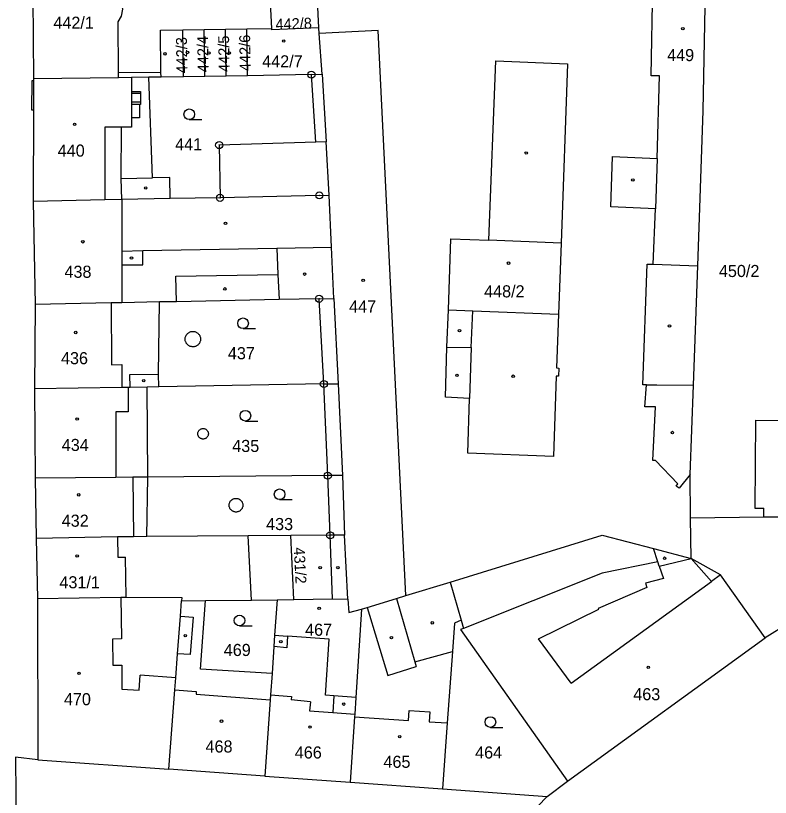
# Model space of a CAD drawing. Extents: x -733394 to -722299, y -1082822 to -1075049.
# Drawn here: x -728472.7 to -728366.6, y -1079581.1 to -1079471.2 of the extents above; entities that cross this region are included whole.
import ezdxf

# ---------------------------------------------------------------- set-up
doc = ezdxf.new("R2010")
doc.units = 0
for name, color, linetype in [('Hranice parcel', 7, 'Continuous'), ('Parcelní čísla', 7, 'Continuous'), ('Vnitřní kresba', 7, 'Continuous'), ('Značky bodu BP', 7, 'Continuous'), ('Značky budov', 7, 'Continuous'), ('Značky kultur', 7, 'Continuous')]:
    doc.layers.add(name, color=color, linetype=linetype)

msp = doc.modelspace()

# ---------------------------------------------------------------- linework, layer by layer
at = {"layer": 'Hranice parcel'}
for p, q in [((-728470.32, -1079459.36), (-728470.14, -1079480.06)), ((-728436.69, -1079472.97), (-728436.85, -1079469.29)), ((-728430.09, -1079472.87), (-728430.25, -1079469.02)), ((-728449.18, -1079473.15), (-728446.18, -1079473.11)), ((-728449.09, -1079479.75), (-728449.18, -1079473.15)), ((-728446.18, -1079473.11), (-728443.18, -1079473.06)), ((-728446.09, -1079479.71), (-728446.18, -1079473.11)), ((-728443.18, -1079473.06), (-728440.18, -1079473.02)), ((-728443.09, -1079479.66), (-728443.18, -1079473.06)), ((-728440.18, -1079473.02), (-728436.69, -1079472.97)), ((-728440.09, -1079479.62), (-728440.18, -1079473.02)), ((-728430.03, -1079473.65), (-728430.09, -1079472.87)), ((-728458.24, -1079479.88), (-728470.14, -1079480.06)), ((-728452.24, -1079479.8), (-728453.95, -1079479.8)), ((-728449.09, -1079479.75), (-728452.24, -1079479.8)), ((-728446.09, -1079479.71), (-728449.09, -1079479.75)), ((-728443.09, -1079479.66), (-728446.09, -1079479.71)), ((-728440.09, -1079479.62), (-728443.09, -1079479.66)), ((-728431.11, -1079479.45), (-728440.09, -1079479.62)), ((-728430.49, -1079488.97), (-728431.11, -1079479.45)), ((-728470.19, -1079497.28), (-728469.94, -1079511.77)), ((-728429.36, -1079522.95), (-728430.03, -1079510.97)), ((-728469.94, -1079511.77), (-728470.02, -1079523.65)), ((-728452.57, -1079523.35), (-728454.17, -1079523.38)), ((-728454.11, -1079536.05), (-728454.17, -1079523.38)), ((-728429.36, -1079522.95), (-728452.57, -1079523.35)), ((-728428.81, -1079535.84), (-728429.36, -1079522.95)), ((-728470.02, -1079523.65), (-728469.93, -1079536.19)), ((-728469.93, -1079536.19), (-728469.77, -1079544.69)), ((-728454.25, -1079544.41), (-728454.11, -1079536.05)), ((-728428.81, -1079535.84), (-728454.11, -1079536.05)), ((-728428.47, -1079544.23), (-728428.81, -1079535.84)), ((-728377.86, -1079541.79), (-728377.89, -1079535.66)), ((-728335.66, -1079539.03), (-728367.36, -1079558.62)), ((-728377.75, -1079547.49), (-728377.86, -1079541.79)), ((-728428.17, -1079553.18), (-728428.47, -1079544.23)), ((-728469.77, -1079544.69), (-728469.62, -1079553.11)), ((-728439.98, -1079544.31), (-728454.25, -1079544.41)), ((-728439.55, -1079553.33), (-728439.98, -1079544.31)), ((-728417.86, -1079552.71), (-728411.64, -1079550.81)), ((-728411.64, -1079550.81), (-728410.09, -1079556.17)), ((-728469.62, -1079553.11), (-728469.57, -1079575.82)), ((-728449.37, -1079553.45), (-728445.98, -1079553.41)), ((-728445.98, -1079553.41), (-728439.55, -1079553.33)), ((-728439.55, -1079553.33), (-728435.93, -1079553.28)), ((-728424.06, -1079554.6), (-728424.87, -1079567.02)), ((-728395.11, -1079578.82), (-728367.36, -1079558.62)), ((-728436.39, -1079559.88), (-728436.65, -1079563.67)), ((-728469.57, -1079575.82), (-728451.13, -1079577.12)), ((-728437.66, -1079578.09), (-728451.13, -1079577.12)), ((-728437.66, -1079578.09), (-728425.65, -1079578.94)), ((-728425.65, -1079578.94), (-728412.71, -1079579.86)), ((-728398.01, -1079580.93), (-728395.11, -1079578.82)), ((-728412.71, -1079579.86), (-728398.01, -1079580.93)), ((-728398.01, -1079580.93), (-728407.52, -1079590.83))]:
    msp.add_line(p, q, dxfattribs=at)
for points in [[(-728377.89, -1079535.66), (-728379.46, -1079537.61), (-728379.86, -1079537.3), (-728379.63, -1079537), (-728382.77, -1079533.71), (-728383.15, -1079533.73), (-728382.75, -1079526.18), (-728384.26, -1079526.14), (-728384.05, -1079523.07), (-728384.55, -1079523.06), (-728383.93, -1079506.08), (-728383.08, -1079506.09), (-728382.78, -1079498.3), (-728389.06, -1079498.02), (-728388.8, -1079490.97), (-728382.54, -1079491.22), (-728382.21, -1079479.61), (-728383.37, -1079479.6), (-728382.92, -1079454.06), (-728382.9, -1079452.81), (-728381.27, -1079452.84), (-728381.29, -1079454.07), (-728375.5, -1079454.1)], [(-728458.24, -1079479.88), (-728458.24, -1079479.17), (-728458.28, -1079472.03), (-728457.78, -1079471.24), (-728457.59, -1079470.26), (-728457.79, -1079469.27), (-728458.3, -1079468.49), (-728458.34, -1079460.95)], [(-728377.89, -1079535.66), (-728377.44, -1079523.13), (-728376.84, -1079506.33), (-728376.06, -1079484.54), (-728375.78, -1079469.87)], [(-728452.24, -1079479.8), (-728452.25, -1079479.09), (-728452.33, -1079473.2), (-728449.18, -1079473.15)], [(-728430.09, -1079472.87), (-728436.69, -1079473.14), (-728436.69, -1079472.97)], [(-728431.11, -1079479.45), (-728429.6, -1079479.37), (-728430.03, -1079473.65)], [(-728417.86, -1079552.71), (-728421.74, -1079473.24), (-728430.03, -1079473.65)], [(-728396.38, -1079521.86), (-728396.71, -1079521.85), (-728397.12, -1079533.13), (-728409.15, -1079532.69), (-728408.9, -1079525.01), (-728412.29, -1079524.82), (-728412.07, -1079517.77), (-728411.86, -1079512.54), (-728411.51, -1079502.52), (-728406.17, -1079502.74), (-728405.22, -1079477.52), (-728395.12, -1079477.92), (-728396.03, -1079503.15), (-728396.39, -1079513.11), (-728396.67, -1079520.7), (-728396.34, -1079520.71), (-728396.38, -1079521.86)], [(-728470.14, -1079480.06), (-728470.14, -1079480.32), (-728470.15, -1079484.39), (-728470.19, -1079497.28)], [(-728453.95, -1079479.8), (-728456.4, -1079479.85), (-728458.24, -1079479.88)], [(-728450.95, -1079496.87), (-728451.01, -1079493.91), (-728453.42, -1079493.97), (-728453.95, -1079479.8)], [(-728430.49, -1079488.97), (-728444.07, -1079489.36), (-728443.95, -1079496.78), (-728450.95, -1079496.87)], [(-728430.03, -1079510.97), (-728427.96, -1079510.93), (-728428.29, -1079503.71), (-728428.62, -1079496.4), (-728429.05, -1079488.91), (-728430.49, -1079488.97)], [(-728450.95, -1079496.87), (-728457.76, -1079497.02), (-728460.16, -1079497.07), (-728470.19, -1079497.28)], [(-728430.03, -1079510.97), (-728435.66, -1079511.09), (-728450.08, -1079511.38), (-728452.47, -1079511.42)], [(-728452.47, -1079511.42), (-728457.73, -1079511.53), (-728459.27, -1079511.56), (-728469.94, -1079511.77)], [(-728452.57, -1079523.35), (-728452.6, -1079521.55), (-728452.47, -1079511.42)], [(-728454.17, -1079523.38), (-728456.59, -1079523.42), (-728456.86, -1079523.42), (-728457.73, -1079523.44), (-728470.02, -1079523.65)], [(-728454.11, -1079536.05), (-728456.21, -1079536.07), (-728458.59, -1079536.09), (-728469.93, -1079536.19)], [(-728377.86, -1079541.79), (-728367.56, -1079541.61), (-728364.95, -1079541.61)], [(-728428.47, -1079544.23), (-728433.99, -1079544.27), (-728439.98, -1079544.31)], [(-728411.64, -1079550.81), (-728390.24, -1079544.2), (-728383.07, -1079546.09), (-728377.75, -1079547.49)], [(-728454.25, -1079544.41), (-728456.12, -1079544.42), (-728458.35, -1079544.44), (-728469.77, -1079544.69)], [(-728367.36, -1079558.62), (-728373.64, -1079549.8), (-728377.75, -1079547.49)], [(-728469.62, -1079553.11), (-728457.87, -1079552.94), (-728457.16, -1079552.94), (-728449.34, -1079552.99), (-728449.37, -1079553.45)], [(-728424.06, -1079554.6), (-728423.29, -1079554.37), (-728419.14, -1079553.1), (-728417.86, -1079552.71)], [(-728451.13, -1079577.12), (-728450.3, -1079565.95), (-728450.18, -1079564.26), (-728449.92, -1079560.87), (-728449.53, -1079555.61), (-728449.37, -1079553.45)], [(-728436.65, -1079563.67), (-728446.69, -1079563.03), (-728445.98, -1079553.41)], [(-728435.93, -1079553.28), (-728436.28, -1079558.28), (-728436.39, -1079559.88)], [(-728435.93, -1079553.28), (-728433.57, -1079553.25), (-728428.17, -1079553.18)], [(-728428.17, -1079553.18), (-728425.99, -1079553.21), (-728425.84, -1079555.09), (-728424.06, -1079554.6)], [(-728410.09, -1079556.17), (-728410.99, -1079556.59), (-728411.28, -1079560.58), (-728412.03, -1079570.61), (-728412.71, -1079579.86)], [(-728410.09, -1079556.17), (-728409.76, -1079557.31), (-728410.15, -1079557.47), (-728395.11, -1079578.82)], [(-728424.87, -1079567.02), (-728427.95, -1079566.8), (-728429.15, -1079566.71), (-728428.62, -1079558.81), (-728434.45, -1079558.41), (-728434.57, -1079560.04), (-728436.39, -1079559.88)], [(-728436.65, -1079563.67), (-728436.86, -1079566.68), (-728436.91, -1079567.34), (-728437.66, -1079578.09)], [(-728424.87, -1079567.02), (-728425.02, -1079569.36), (-728425.05, -1079569.76), (-728425.65, -1079578.94)], [(-728469.57, -1079575.82), (-728472.67, -1079575.42), (-728472.62, -1079586.13)]]:
    msp.add_lwpolyline(points, dxfattribs=at)
at = {"layer": 'Vnitřní kresba'}
for p, q in [((-728458.24, -1079479.17), (-728452.25, -1079479.09)), ((-728429.6, -1079479.37), (-728429.05, -1079488.91)), ((-728470.41, -1079480.32), (-728470.42, -1079484.39)), ((-728470.14, -1079480.32), (-728470.41, -1079480.32)), ((-728456.4, -1079479.85), (-728456.4, -1079481.81)), ((-728456.4, -1079481.81), (-728456.4, -1079482.11)), ((-728456.4, -1079481.81), (-728455.15, -1079481.81)), ((-728455.15, -1079482.11), (-728456.4, -1079482.11)), ((-728456.4, -1079482.11), (-728456.4, -1079483.34)), ((-728455.15, -1079481.81), (-728455.15, -1079482.11)), ((-728455.15, -1079482.11), (-728455.15, -1079483.34)), ((-728455.15, -1079483.34), (-728456.4, -1079483.34)), ((-728456.4, -1079483.34), (-728456.4, -1079483.64)), ((-728455.29, -1079483.64), (-728456.4, -1079483.64)), ((-728456.4, -1079483.64), (-728456.4, -1079485.51)), ((-728455.15, -1079483.64), (-728455.29, -1079483.64)), ((-728455.29, -1079483.64), (-728455.29, -1079485.51)), ((-728455.15, -1079483.34), (-728455.15, -1079483.64)), ((-728470.42, -1079484.39), (-728470.15, -1079484.39)), ((-728455.29, -1079485.51), (-728456.4, -1079485.51)), ((-728456.4, -1079485.51), (-728456.4, -1079486.83)), ((-728460.15, -1079486.83), (-728460.16, -1079497.07)), ((-728457.8, -1079486.83), (-728460.15, -1079486.83)), ((-728457.83, -1079494.07), (-728457.8, -1079486.83)), ((-728456.4, -1079486.83), (-728457.8, -1079486.83)), ((-728382.54, -1079491.22), (-728382.78, -1079498.3)), ((-728457.83, -1079494.07), (-728453.42, -1079493.97)), ((-728457.76, -1079497.02), (-728457.83, -1079494.07)), ((-728457.76, -1079497.02), (-728457.75, -1079504.26)), ((-728430, -1079496.43), (-728443.95, -1079496.78)), ((-728430, -1079496.43), (-728428.62, -1079496.4)), ((-728396.03, -1079503.15), (-728406.17, -1079502.74)), ((-728457.75, -1079504.26), (-728454.78, -1079504.2)), ((-728457.75, -1079504.26), (-728457.74, -1079506.18)), ((-728454.79, -1079506.2), (-728454.78, -1079504.2)), ((-728454.78, -1079504.2), (-728435.99, -1079503.85)), ((-728435.99, -1079503.85), (-728428.29, -1079503.71)), ((-728435.99, -1079503.85), (-728435.82, -1079507.57)), ((-728457.74, -1079506.18), (-728457.73, -1079511.53)), ((-728457.74, -1079506.18), (-728454.79, -1079506.2)), ((-728383.08, -1079506.09), (-728376.84, -1079506.33)), ((-728450.17, -1079507.78), (-728435.82, -1079507.57)), ((-728450.08, -1079511.38), (-728450.17, -1079507.78)), ((-728435.82, -1079507.57), (-728435.66, -1079511.09)), ((-728427.96, -1079510.93), (-728427.36, -1079522.92)), ((-728459.27, -1079511.56), (-728459.2, -1079520.24)), ((-728411.86, -1079512.54), (-728408.44, -1079512.67)), ((-728408.66, -1079517.83), (-728408.44, -1079512.67)), ((-728408.44, -1079512.67), (-728396.39, -1079513.11)), ((-728412.07, -1079517.77), (-728408.66, -1079517.83)), ((-728408.66, -1079517.83), (-728408.9, -1079525.01)), ((-728459.2, -1079520.24), (-728457.75, -1079520.23)), ((-728457.75, -1079520.23), (-728457.73, -1079523.44)), ((-728456.62, -1079521.62), (-728452.6, -1079521.55)), ((-728456.59, -1079523.42), (-728456.62, -1079521.62)), ((-728429.36, -1079522.95), (-728427.36, -1079522.92)), ((-728427.36, -1079522.92), (-728426.76, -1079535.82)), ((-728384.05, -1079523.07), (-728382.58, -1079523.08)), ((-728382.58, -1079523.08), (-728377.44, -1079523.13)), ((-728456.86, -1079523.42), (-728456.86, -1079526.86)), ((-728458.58, -1079526.85), (-728458.59, -1079536.09)), ((-728456.86, -1079526.86), (-728458.58, -1079526.85)), ((-728368.71, -1079528.02), (-728368.79, -1079540.4)), ((-728368.71, -1079528.02), (-728364.86, -1079528.07)), ((-728456.21, -1079536.07), (-728456.12, -1079544.42)), ((-728426.76, -1079535.82), (-728428.81, -1079535.84)), ((-728426.76, -1079535.82), (-728426.45, -1079544.22)), ((-728368.79, -1079540.4), (-728367.56, -1079540.41)), ((-728367.56, -1079541.61), (-728367.56, -1079540.41)), ((-728433.57, -1079553.25), (-728433.99, -1079544.27)), ((-728426.45, -1079544.22), (-728428.47, -1079544.23)), ((-728425.99, -1079553.21), (-728426.45, -1079544.22)), ((-728458.35, -1079544.44), (-728458.32, -1079547.29)), ((-728382.44, -1079547.96), (-728383.07, -1079546.09)), ((-728458.32, -1079547.29), (-728457.22, -1079547.28)), ((-728457.16, -1079552.94), (-728457.22, -1079547.28)), ((-728382.23, -1079548.58), (-728377.75, -1079547.49)), ((-728377.75, -1079547.49), (-728374.91, -1079550.7)), ((-728382.44, -1079547.96), (-728390.26, -1079549.54)), ((-728382.23, -1079548.58), (-728382.44, -1079547.96)), ((-728382.23, -1079548.58), (-728381.65, -1079550.3)), ((-728390.26, -1079549.54), (-728409.76, -1079557.31)), ((-728394.63, -1079565.01), (-728374.91, -1079550.7)), ((-728381.65, -1079550.3), (-728384.18, -1079550.97)), ((-728373.64, -1079549.8), (-728374.91, -1079550.7)), ((-728384, -1079551.57), (-728390.82, -1079554.53)), ((-728384.18, -1079550.97), (-728384, -1079551.57)), ((-728457.87, -1079552.94), (-728457.81, -1079558.79)), ((-728419.14, -1079553.1), (-728416.59, -1079562.04)), ((-728423.29, -1079554.37), (-728420.36, -1079563.96)), ((-728399.2, -1079558.8), (-728390.75, -1079554.62)), ((-728390.82, -1079554.53), (-728390.75, -1079554.62)), ((-728449.53, -1079555.61), (-728447.75, -1079555.74)), ((-728447.75, -1079555.74), (-728448.14, -1079561)), ((-728436.28, -1079558.28), (-728434.45, -1079558.41)), ((-728457.81, -1079558.79), (-728459.05, -1079558.81)), ((-728459.05, -1079558.81), (-728459.01, -1079562.48)), ((-728394.63, -1079565.01), (-728399.2, -1079558.8)), ((-728416.59, -1079562.04), (-728411.28, -1079560.58)), ((-728448.14, -1079561), (-728449.92, -1079560.87)), ((-728459.01, -1079562.48), (-728457.77, -1079562.47)), ((-728457.77, -1079562.47), (-728457.73, -1079565.84)), ((-728420.36, -1079563.96), (-728416.41, -1079562.67)), ((-728416.59, -1079562.04), (-728416.41, -1079562.67)), ((-728455.32, -1079566.02), (-728455.16, -1079563.89)), ((-728450.18, -1079564.26), (-728455.16, -1079563.89)), ((-728457.73, -1079565.84), (-728455.32, -1079566.02)), ((-728450.3, -1079565.95), (-728447.29, -1079566.17)), ((-728447.29, -1079566.17), (-728447.32, -1079566.57)), ((-728447.32, -1079566.57), (-728436.91, -1079567.34)), ((-728436.86, -1079566.68), (-728433.91, -1079566.89)), ((-728433.91, -1079566.89), (-728433.95, -1079567.35)), ((-728431.24, -1079567.62), (-728433.95, -1079567.35)), ((-728427.95, -1079566.8), (-728428.12, -1079569.13)), ((-728431.24, -1079567.62), (-728431.36, -1079568.89)), ((-728431.36, -1079568.89), (-728428.12, -1079569.13)), ((-728428.12, -1079569.13), (-728425.02, -1079569.36)), ((-728417.47, -1079570.25), (-728417.38, -1079568.86)), ((-728417.38, -1079568.86), (-728414.46, -1079569.05)), ((-728414.46, -1079569.05), (-728414.55, -1079570.45)), ((-728425.05, -1079569.76), (-728417.47, -1079570.25)), ((-728414.55, -1079570.45), (-728412.03, -1079570.61))]:
    msp.add_line(p, q, dxfattribs=at)
for points in [[(-728447.77, -1079517.72), (-728447.86, -1079517.72), (-728447.95, -1079517.7), (-728448.04, -1079517.69), (-728448.13, -1079517.66), (-728448.22, -1079517.62), (-728448.3, -1079517.58), (-728448.38, -1079517.54), (-728448.45, -1079517.48), (-728448.52, -1079517.42), (-728448.58, -1079517.35), (-728448.64, -1079517.28), (-728448.69, -1079517.21), (-728448.73, -1079517.13), (-728448.77, -1079517.04), (-728448.8, -1079516.96), (-728448.83, -1079516.87), (-728448.84, -1079516.78), (-728448.85, -1079516.69), (-728448.85, -1079516.59), (-728448.84, -1079516.5), (-728448.83, -1079516.41), (-728448.8, -1079516.32), (-728448.77, -1079516.24), (-728448.73, -1079516.15), (-728448.69, -1079516.07), (-728448.64, -1079516), (-728448.58, -1079515.93), (-728448.52, -1079515.86), (-728448.45, -1079515.8), (-728448.38, -1079515.75), (-728448.3, -1079515.7), (-728448.22, -1079515.66), (-728448.13, -1079515.62), (-728448.04, -1079515.59), (-728447.95, -1079515.58), (-728447.86, -1079515.56), (-728447.77, -1079515.56)], [(-728447.77, -1079515.56), (-728447.68, -1079515.56), (-728447.59, -1079515.57), (-728447.5, -1079515.59), (-728447.41, -1079515.62), (-728447.32, -1079515.66), (-728447.24, -1079515.7), (-728447.16, -1079515.74), (-728447.09, -1079515.8), (-728447.02, -1079515.86), (-728446.96, -1079515.93), (-728446.9, -1079516), (-728446.85, -1079516.07), (-728446.8, -1079516.15), (-728446.77, -1079516.24), (-728446.73, -1079516.32), (-728446.71, -1079516.41), (-728446.7, -1079516.5), (-728446.69, -1079516.59), (-728446.69, -1079516.69), (-728446.7, -1079516.78), (-728446.71, -1079516.87), (-728446.73, -1079516.96), (-728446.77, -1079517.04), (-728446.8, -1079517.13), (-728446.85, -1079517.21), (-728446.9, -1079517.28), (-728446.96, -1079517.35), (-728447.02, -1079517.42), (-728447.09, -1079517.48), (-728447.16, -1079517.54), (-728447.24, -1079517.58), (-728447.32, -1079517.62), (-728447.41, -1079517.66), (-728447.5, -1079517.69), (-728447.59, -1079517.71), (-728447.68, -1079517.72), (-728447.77, -1079517.72)], [(-728446.33, -1079530.69), (-728446.41, -1079530.69), (-728446.48, -1079530.68), (-728446.55, -1079530.66), (-728446.62, -1079530.63), (-728446.69, -1079530.6), (-728446.75, -1079530.56), (-728446.81, -1079530.51), (-728446.87, -1079530.46), (-728446.92, -1079530.4), (-728446.96, -1079530.34), (-728446.99, -1079530.28), (-728447.02, -1079530.21), (-728447.05, -1079530.14), (-728447.06, -1079530.06), (-728447.07, -1079529.99), (-728447.07, -1079529.91), (-728447.06, -1079529.84), (-728447.05, -1079529.77), (-728447.02, -1079529.69), (-728446.99, -1079529.62), (-728446.96, -1079529.56), (-728446.92, -1079529.5), (-728446.87, -1079529.44), (-728446.81, -1079529.39), (-728446.75, -1079529.34), (-728446.69, -1079529.3), (-728446.62, -1079529.27), (-728446.55, -1079529.24), (-728446.48, -1079529.23), (-728446.41, -1079529.21), (-728446.33, -1079529.21)], [(-728446.33, -1079529.21), (-728446.26, -1079529.21), (-728446.18, -1079529.23), (-728446.11, -1079529.24), (-728446.04, -1079529.27), (-728445.97, -1079529.3), (-728445.91, -1079529.34), (-728445.85, -1079529.39), (-728445.79, -1079529.44), (-728445.74, -1079529.5), (-728445.7, -1079529.56), (-728445.66, -1079529.62), (-728445.64, -1079529.69), (-728445.61, -1079529.76), (-728445.6, -1079529.84), (-728445.59, -1079529.91), (-728445.59, -1079529.99), (-728445.6, -1079530.06), (-728445.61, -1079530.14), (-728445.64, -1079530.21), (-728445.66, -1079530.28), (-728445.7, -1079530.34), (-728445.74, -1079530.4), (-728445.79, -1079530.46), (-728445.85, -1079530.51), (-728445.91, -1079530.56), (-728445.97, -1079530.6), (-728446.04, -1079530.63), (-728446.11, -1079530.66), (-728446.18, -1079530.68), (-728446.26, -1079530.69), (-728446.33, -1079530.69)], [(-728441.71, -1079540.95), (-728441.8, -1079540.95), (-728441.88, -1079540.94), (-728441.97, -1079540.92), (-728442.05, -1079540.89), (-728442.13, -1079540.85), (-728442.2, -1079540.81), (-728442.27, -1079540.77), (-728442.34, -1079540.71), (-728442.4, -1079540.65), (-728442.46, -1079540.59), (-728442.51, -1079540.52), (-728442.56, -1079540.45), (-728442.59, -1079540.37), (-728442.62, -1079540.29), (-728442.65, -1079540.2), (-728442.66, -1079540.12), (-728442.67, -1079540.03), (-728442.67, -1079539.95), (-728442.66, -1079539.86), (-728442.65, -1079539.78), (-728442.62, -1079539.69), (-728442.59, -1079539.61), (-728442.56, -1079539.54), (-728442.51, -1079539.46), (-728442.46, -1079539.39), (-728442.4, -1079539.33), (-728442.34, -1079539.27), (-728442.27, -1079539.21), (-728442.2, -1079539.17), (-728442.13, -1079539.12), (-728442.05, -1079539.09), (-728441.97, -1079539.06), (-728441.88, -1079539.05), (-728441.8, -1079539.03), (-728441.71, -1079539.03)], [(-728441.71, -1079539.03), (-728441.62, -1079539.03), (-728441.54, -1079539.05), (-728441.45, -1079539.06), (-728441.37, -1079539.09), (-728441.29, -1079539.12), (-728441.22, -1079539.17), (-728441.14, -1079539.21), (-728441.08, -1079539.27), (-728441.01, -1079539.32), (-728440.96, -1079539.39), (-728440.91, -1079539.46), (-728440.86, -1079539.53), (-728440.82, -1079539.61), (-728440.79, -1079539.69), (-728440.77, -1079539.78), (-728440.76, -1079539.86), (-728440.75, -1079539.95), (-728440.75, -1079540.03), (-728440.76, -1079540.12), (-728440.77, -1079540.2), (-728440.79, -1079540.29), (-728440.82, -1079540.37), (-728440.86, -1079540.45), (-728440.91, -1079540.52), (-728440.96, -1079540.59), (-728441.01, -1079540.66), (-728441.08, -1079540.71), (-728441.14, -1079540.77), (-728441.22, -1079540.81), (-728441.29, -1079540.86), (-728441.37, -1079540.89), (-728441.45, -1079540.92), (-728441.54, -1079540.94), (-728441.62, -1079540.95), (-728441.71, -1079540.95)]]:
    msp.add_lwpolyline(points, dxfattribs=at)
at = {"layer": 'Značky bodu BP'}
for centre, radius in [((-728431.11, -1079479.45), 0.5), ((-728431.11, -1079479.45), 0.0303), ((-728444.07, -1079489.36), 0.5), ((-728444.07, -1079489.36), 0.0303), ((-728430, -1079496.43), 0.5), ((-728443.95, -1079496.78), 0.5), ((-728443.95, -1079496.78), 0.0303), ((-728430, -1079496.43), 0.0303), ((-728430.03, -1079510.97), 0.5), ((-728430.03, -1079510.97), 0.0303), ((-728429.36, -1079522.95), 0.5), ((-728429.36, -1079522.95), 0.0303), ((-728428.81, -1079535.84), 0.5), ((-728428.81, -1079535.84), 0.0303), ((-728428.47, -1079544.23), 0.5), ((-728428.47, -1079544.23), 0.0303)]:
    msp.add_circle(centre, radius, dxfattribs=at)
at = {"layer": 'Značky budov'}
for centre in [(-728378.93, -1079472.99), (-728435.01, -1079474.73), (-728451.69, -1079476.53), (-728448.53, -1079476.33), (-728445.52, -1079476.4), (-728442.65, -1079476.4), (-728464.38, -1079486.43), (-728400.93, -1079490.48), (-728385.95, -1079494.26), (-728454.4, -1079495.39), (-728443.19, -1079500.37), (-728463.23, -1079502.95), (-728456.39, -1079505.24), (-728403.41, -1079505.96), (-728432.07, -1079507.5), (-728423.84, -1079508.37), (-728443.27, -1079509.58), (-728380.8, -1079514.79), (-728464.23, -1079515.71), (-728410.31, -1079515.45), (-728454.68, -1079522.48), (-728410.66, -1079521.73), (-728402.77, -1079521.86), (-728464.02, -1079527.88), (-728380.39, -1079529.78), (-728463.81, -1079538.53), (-728464.02, -1079547.13), (-728381.48, -1079547.45), (-728429.88, -1079548.77), (-728427.39, -1079548.78), (-728430.02, -1079554.5), (-728414.13, -1079556.54), (-728448.84, -1079558.34), (-728419.87, -1079558.62), (-728435.41, -1079559.19), (-728383.78, -1079562.78), (-728463.76, -1079563.63), (-728426.57, -1079567.96), (-728443.74, -1079570.36), (-728431.3, -1079571.19), (-728418.71, -1079572.53)]:
    msp.add_circle(centre, 0.175, dxfattribs=at)
at = {"layer": 'Značky kultur'}
for p, q in [((-728448.27, -1079485.78), (-728446.52, -1079485.78)), ((-728440.72, -1079515.17), (-728438.97, -1079515.17)), ((-728440.39, -1079528.16), (-728438.64, -1079528.16)), ((-728435.58, -1079539.21), (-728433.83, -1079539.21)), ((-728441.21, -1079556.96), (-728439.46, -1079556.96)), ((-728405.97, -1079571.23), (-728404.22, -1079571.23))]:
    msp.add_line(p, q, dxfattribs=at)
for centre in [(-728448.27, -1079485.03), (-728440.72, -1079514.42), (-728440.39, -1079527.41), (-728435.58, -1079538.46), (-728441.21, -1079556.21), (-728405.97, -1079570.48)]:
    msp.add_circle(centre, 0.75, dxfattribs=at)

# ---------------------------------------------------------------- texts
at = {"layer": 'Parcelní čísla'}
for s, p in [('442/1', (-728467.37, -1079473)), ('449', (-728381.13, -1079477.55)), ('442/7', (-728438.03, -1079478.43)), ('440', (-728466.76, -1079490.98)), ('441', (-728450.26, -1079490.09)), ('438', (-728465.81, -1079508.02)), ('450/2', (-728373.86, -1079507.91)), ('448/2', (-728406.85, -1079510.77)), ('447', (-728425.82, -1079512.9)), ('437', (-728442.85, -1079519.47)), ('436', (-728466.3, -1079520.17)), ('434', (-728466.19, -1079532.37)), ('435', (-728442.24, -1079532.51)), ('432', (-728466.2, -1079543.02)), ('433', (-728437.48, -1079543.49)), ('431/1', (-728466.52, -1079551.68)), ('467', (-728432, -1079558.35)), ('469', (-728443.43, -1079561.2)), ('463', (-728385.89, -1079567.42)), ('470', (-728465.89, -1079568.12)), ('468', (-728445.99, -1079574.77)), ('466', (-728433.45, -1079575.61)), ('464', (-728408.11, -1079575.61)), ('465', (-728420.99, -1079576.92))]:
    msp.add_text(s, height=1.7, dxfattribs=at).set_placement(p)
for s, rotation, p in [('442/8', 2, (-728436.14, -1079473.14)), ('442/6', 91, (-728439.64, -1079478.94)), ('442/3', 91, (-728448.53, -1079479.28)), ('442/4', 91, (-728445.55, -1079479.11)), ('442/5', 91, (-728442.6, -1079479.06)), ('431/2', 273, (-728433.6, -1079545.96))]:
    msp.add_text(s, height=1.53, rotation=rotation, dxfattribs=at).set_placement(p)

doc.saveas('drawing.dxf')
